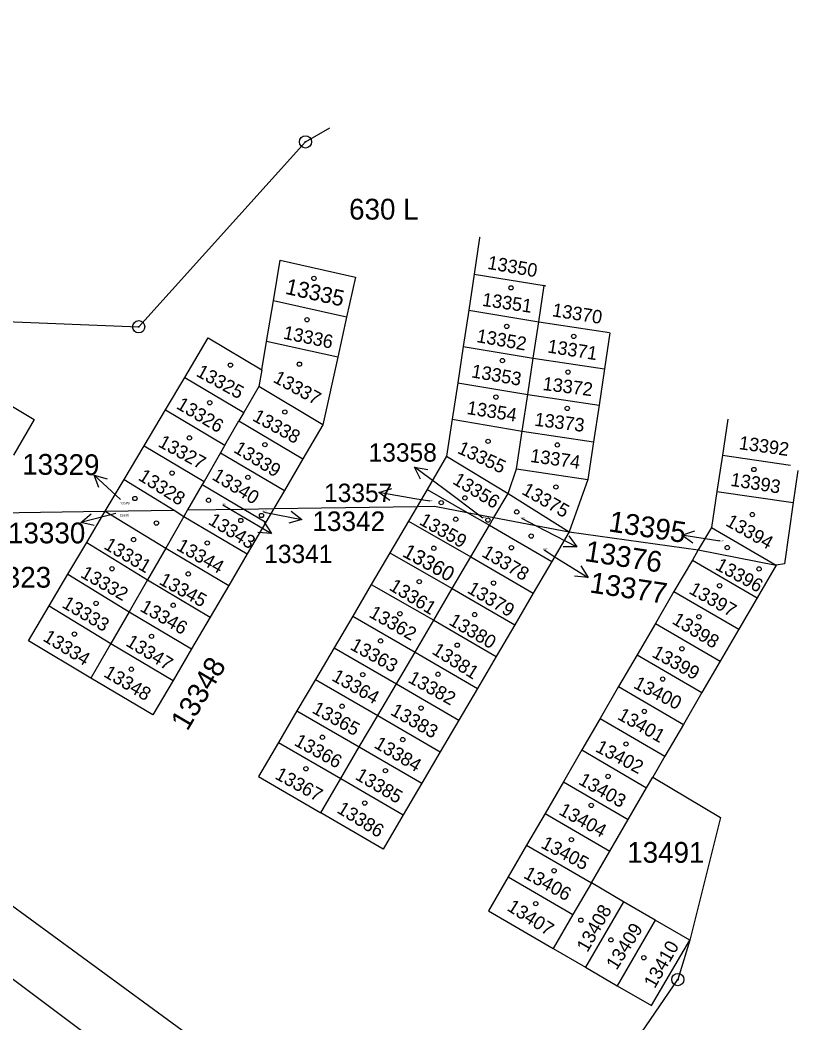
# Model space of a CAD drawing. Extents: x -825057 to -819383, y -1071633 to -1067888.
# Drawn here: x -820277 to -820213.4, y -1071568.9 to -1071486.9 of the extents above; entities that cross this region are included whole.
import ezdxf

# ---------------------------------------------------------------- set-up
doc = ezdxf.new("R2010")
doc.units = 0
for name, color, linetype in [('Vrstva 1', 7, 'Continuous'), ('Vrstva 10', 7, 'Continuous'), ('Vrstva 13', 7, 'Continuous'), ('Vrstva 16', 7, 'Continuous'), ('Vrstva 17', 7, 'Continuous'), ('Vrstva 18', 7, 'Continuous'), ('Vrstva 19', 7, 'Continuous'), ('Vrstva 24', 7, 'Continuous'), ('Vrstva 25', 7, 'Continuous')]:
    doc.layers.add(name, color=color, linetype=linetype)

msp = doc.modelspace()

# ---------------------------------------------------------------- linework, layer by layer
at = {"layer": 'Vrstva 1'}
for p, q in [((-820253.69, -1071496.85), (-820251.69, -1071495.69)), ((-820267.33, -1071511.96), (-820253.69, -1071496.85)), ((-820239.46, -1071504.68), (-820239.91, -1071507.65)), ((-820239.45, -1071504.65), (-820239.46, -1071504.68)), ((-820239.46, -1071504.68), (-820239.4, -1071504.69)), ((-820256.32, -1071509.84), (-820255.75, -1071506.52)), ((-820255.75, -1071506.52), (-820249.6, -1071507.9)), ((-820249.6, -1071507.9), (-820250.33, -1071511.17)), ((-820239.91, -1071507.65), (-820240.35, -1071510.61)), ((-820239.91, -1071507.65), (-820234.17, -1071508.6)), ((-820234.62, -1071511.57), (-820234.17, -1071508.6)), ((-820234.17, -1071508.6), (-820234.16, -1071508.53)), ((-820234.17, -1071508.6), (-820234.04, -1071508.62)), ((-820256.89, -1071513.16), (-820256.32, -1071509.84)), ((-820250.33, -1071511.17), (-820256.32, -1071509.84)), ((-820250.33, -1071511.17), (-820251.05, -1071514.46)), ((-820240.35, -1071510.61), (-820240.8, -1071513.58)), ((-820240.35, -1071510.61), (-820234.62, -1071511.57)), ((-820284.31, -1071511.28), (-820267.33, -1071511.96)), ((-820235.07, -1071514.53), (-820234.62, -1071511.57)), ((-820234.62, -1071511.57), (-820228.83, -1071512.44)), ((-820263.57, -1071516.1), (-820261.65, -1071512.87)), ((-820261.65, -1071512.87), (-820257.25, -1071515.49)), ((-820228.8, -1071512.45), (-820229.24, -1071515.41)), ((-820257.25, -1071515.49), (-820256.89, -1071513.16)), ((-820251.05, -1071514.46), (-820256.89, -1071513.16)), ((-820240.8, -1071513.58), (-820241.25, -1071516.55)), ((-820240.8, -1071513.58), (-820235.07, -1071514.53)), ((-820251.05, -1071514.46), (-820252.28, -1071519.99)), ((-820235.52, -1071517.5), (-820235.07, -1071514.53)), ((-820235.07, -1071514.53), (-820229.24, -1071515.41)), ((-820265.15, -1071518.76), (-820263.57, -1071516.1)), ((-820263.57, -1071516.1), (-820258.73, -1071518.97)), ((-820257.25, -1071515.49), (-820257.52, -1071516.84)), ((-820229.24, -1071515.41), (-820229.69, -1071518.37)), ((-820281.37, -1071516.28), (-820275.87, -1071519.55)), ((-820257.52, -1071516.84), (-820258.73, -1071518.97)), ((-820252.28, -1071519.99), (-820257.52, -1071516.84)), ((-820241.25, -1071516.55), (-820241.7, -1071519.51)), ((-820241.25, -1071516.55), (-820235.52, -1071517.5)), ((-820235.97, -1071520.5), (-820235.52, -1071517.5)), ((-820235.52, -1071517.5), (-820229.69, -1071518.37)), ((-820229.69, -1071518.37), (-820230.14, -1071521.37)), ((-820266.88, -1071521.69), (-820265.15, -1071518.76)), ((-820265.15, -1071518.76), (-820260.28, -1071521.64)), ((-820258.73, -1071518.97), (-820259.14, -1071519.66)), ((-820275.87, -1071519.55), (-820277.57, -1071522.47)), ((-820260.28, -1071521.64), (-820259.14, -1071519.66)), ((-820259.14, -1071519.66), (-820253.9, -1071522.76)), ((-820252.28, -1071519.99), (-820253.9, -1071522.76)), ((-820241.7, -1071519.51), (-820242.16, -1071522.55)), ((-820241.7, -1071519.51), (-820235.97, -1071520.5)), ((-820219.16, -1071519.52), (-820219.61, -1071522.46)), ((-820236.43, -1071523.58), (-820235.97, -1071520.5)), ((-820235.97, -1071520.5), (-820230.14, -1071521.37)), ((-820268.52, -1071524.44), (-820266.88, -1071521.69)), ((-820266.88, -1071521.69), (-820261.98, -1071524.6)), ((-820260.28, -1071521.64), (-820260.64, -1071522.26)), ((-820230.14, -1071521.37), (-820230.6, -1071524.46)), ((-820260.64, -1071522.26), (-820261.98, -1071524.6)), ((-820260.64, -1071522.26), (-820255.42, -1071525.35)), ((-820242.16, -1071522.55), (-820243.75, -1071525.27)), ((-820242.16, -1071522.55), (-820237.13, -1071525.6)), ((-820219.61, -1071522.46), (-820220.07, -1071525.43)), ((-820219.61, -1071522.46), (-820214.04, -1071523.27)), ((-820253.9, -1071522.76), (-820255.42, -1071525.35)), ((-820237.13, -1071525.6), (-820236.43, -1071523.58)), ((-820236.43, -1071523.58), (-820230.6, -1071524.46)), ((-820270.06, -1071527.04), (-820268.52, -1071524.44)), ((-820268.52, -1071524.44), (-820264.44, -1071526.96)), ((-820262.13, -1071524.86), (-820263.33, -1071526.94)), ((-820261.98, -1071524.6), (-820262.13, -1071524.86)), ((-820262.13, -1071524.86), (-820258.74, -1071526.87)), ((-820230.6, -1071524.46), (-820232.13, -1071528.73)), ((-820255.42, -1071525.35), (-820256.28, -1071526.83)), ((-820243.75, -1071525.27), (-820244.57, -1071526.65)), ((-820243.75, -1071525.27), (-820240.47, -1071527.14)), ((-820238.28, -1071527.56), (-820237.13, -1071525.6)), ((-820237.13, -1071525.6), (-820232.13, -1071528.73)), ((-820220.07, -1071525.43), (-820220.51, -1071528.36)), ((-820220.07, -1071525.43), (-820213.81, -1071526.34)), ((-820258.74, -1071526.87), (-820256.28, -1071526.83)), ((-820256.28, -1071526.83), (-820256.94, -1071527.94)), ((-820256.28, -1071526.83), (-820244.57, -1071526.65)), ((-820244.57, -1071526.65), (-820245.27, -1071527.85)), ((-820244.57, -1071526.65), (-820243.15, -1071526.63)), ((-820243.15, -1071526.63), (-820240.47, -1071527.14)), ((-820280.32, -1071527.2), (-820270.06, -1071527.04)), ((-820271.58, -1071529.6), (-820270.06, -1071527.04)), ((-820270.06, -1071527.04), (-820264.44, -1071526.96)), ((-820270.06, -1071527.04), (-820265.12, -1071530.06)), ((-820263.63, -1071527.46), (-820265.12, -1071530.06)), ((-820264.44, -1071526.96), (-820263.63, -1071527.46)), ((-820263.33, -1071526.94), (-820263.63, -1071527.46)), ((-820263.63, -1071527.46), (-820258.45, -1071530.53)), ((-820263.33, -1071526.94), (-820258.74, -1071526.87)), ((-820258.74, -1071526.87), (-820256.94, -1071527.94)), ((-820240.47, -1071527.14), (-820238.65, -1071528.18)), ((-820240.47, -1071527.14), (-820238.28, -1071527.56)), ((-820238.65, -1071528.18), (-820238.28, -1071527.56)), ((-820238.28, -1071527.56), (-820232.13, -1071528.73)), ((-820256.94, -1071527.94), (-820258.45, -1071530.53)), ((-820245.27, -1071527.85), (-820246.79, -1071530.44)), ((-820245.27, -1071527.85), (-820240.17, -1071530.77)), ((-820240.17, -1071530.77), (-820238.65, -1071528.18)), ((-820238.65, -1071528.18), (-820233.55, -1071531.15)), ((-820220.51, -1071528.36), (-820221.58, -1071530.19)), ((-820220.51, -1071528.36), (-820215.21, -1071531.44)), ((-820232.13, -1071528.73), (-820233.55, -1071531.15)), ((-820232.13, -1071528.73), (-820221.58, -1071530.19)), ((-820273.11, -1071532.18), (-820271.58, -1071529.6)), ((-820271.58, -1071529.6), (-820266.62, -1071532.66)), ((-820265.12, -1071530.06), (-820266.62, -1071532.66)), ((-820265.12, -1071530.06), (-820259.97, -1071533.12)), ((-820258.45, -1071530.53), (-820259.97, -1071533.12)), ((-820246.79, -1071530.44), (-820248.31, -1071533.03)), ((-820246.79, -1071530.44), (-820241.69, -1071533.36)), ((-820241.69, -1071533.36), (-820240.17, -1071530.77)), ((-820240.17, -1071530.77), (-820235.07, -1071533.74)), ((-820221.58, -1071530.19), (-820222.06, -1071531.03)), ((-820221.58, -1071530.19), (-820215.21, -1071531.44)), ((-820233.55, -1071531.15), (-820235.07, -1071533.74)), ((-820222.06, -1071531.03), (-820223.57, -1071533.61)), ((-820222.06, -1071531.03), (-820216.77, -1071534.11)), ((-820274.66, -1071534.78), (-820273.11, -1071532.18)), ((-820273.11, -1071532.18), (-820268.12, -1071535.26)), ((-820266.62, -1071532.66), (-820268.12, -1071535.26)), ((-820266.62, -1071532.66), (-820261.48, -1071535.71)), ((-820259.97, -1071533.12), (-820261.48, -1071535.71)), ((-820248.31, -1071533.03), (-820249.83, -1071535.61)), ((-820248.31, -1071533.03), (-820243.2, -1071535.95)), ((-820243.2, -1071535.95), (-820241.69, -1071533.36)), ((-820241.69, -1071533.36), (-820236.59, -1071536.33)), ((-820235.07, -1071533.74), (-820236.59, -1071536.33)), ((-820223.57, -1071533.61), (-820225.08, -1071536.21)), ((-820223.57, -1071533.61), (-820218.27, -1071536.69)), ((-820276.35, -1071537.64), (-820274.66, -1071534.78)), ((-820274.66, -1071534.78), (-820269.61, -1071537.86)), ((-820268.12, -1071535.26), (-820269.61, -1071537.86)), ((-820268.12, -1071535.26), (-820263, -1071538.3)), ((-820261.48, -1071535.71), (-820263, -1071538.3)), ((-820249.83, -1071535.61), (-820251.35, -1071538.2)), ((-820249.83, -1071535.61), (-820244.73, -1071538.55)), ((-820244.73, -1071538.55), (-820243.2, -1071535.95)), ((-820243.2, -1071535.95), (-820238.11, -1071538.92)), ((-820236.59, -1071536.33), (-820238.11, -1071538.92)), ((-820225.08, -1071536.21), (-820226.58, -1071538.79)), ((-820225.08, -1071536.21), (-820219.78, -1071539.29)), ((-820271.23, -1071540.68), (-820276.35, -1071537.64)), ((-820269.61, -1071537.86), (-820271.23, -1071540.68)), ((-820269.61, -1071537.86), (-820264.52, -1071540.89)), ((-820263, -1071538.3), (-820264.52, -1071540.89)), ((-820251.35, -1071538.2), (-820252.87, -1071540.79)), ((-820251.35, -1071538.2), (-820246.25, -1071541.14)), ((-820246.25, -1071541.14), (-820244.73, -1071538.55)), ((-820244.73, -1071538.55), (-820239.64, -1071541.52)), ((-820238.11, -1071538.92), (-820239.64, -1071541.52)), ((-820226.58, -1071538.79), (-820228.09, -1071541.38)), ((-820226.58, -1071538.79), (-820221.28, -1071541.87)), ((-820266.16, -1071543.69), (-820271.23, -1071540.68)), ((-820264.52, -1071540.89), (-820266.16, -1071543.69)), ((-820252.87, -1071540.79), (-820254.39, -1071543.37)), ((-820252.87, -1071540.79), (-820247.77, -1071543.73)), ((-820247.77, -1071543.73), (-820246.25, -1071541.14)), ((-820246.25, -1071541.14), (-820241.15, -1071544.11)), ((-820239.64, -1071541.52), (-820241.15, -1071544.11)), ((-820228.09, -1071541.38), (-820229.59, -1071543.98)), ((-820228.09, -1071541.38), (-820222.79, -1071544.47)), ((-820254.39, -1071543.37), (-820255.91, -1071545.96)), ((-820254.39, -1071543.37), (-820249.29, -1071546.31)), ((-820249.29, -1071546.31), (-820247.77, -1071543.73)), ((-820247.77, -1071543.73), (-820242.67, -1071546.7)), ((-820229.59, -1071543.98), (-820231.1, -1071546.56)), ((-820229.59, -1071543.98), (-820224.3, -1071547.06)), ((-820241.15, -1071544.11), (-820242.67, -1071546.7)), ((-820255.91, -1071545.96), (-820257.54, -1071548.73)), ((-820255.91, -1071545.96), (-820250.81, -1071548.9)), ((-820250.81, -1071548.9), (-820249.29, -1071546.31)), ((-820249.29, -1071546.31), (-820244.19, -1071549.28)), ((-820242.67, -1071546.7), (-820244.19, -1071549.28)), ((-820231.1, -1071546.56), (-820232.61, -1071549.16)), ((-820231.1, -1071546.56), (-820225.8, -1071549.64)), ((-820257.54, -1071548.73), (-820252.45, -1071551.7)), ((-820252.45, -1071551.7), (-820250.81, -1071548.9)), ((-820250.81, -1071548.9), (-820245.71, -1071551.87)), ((-820225.8, -1071549.64), (-820225.3, -1071548.78)), ((-820244.19, -1071549.28), (-820245.71, -1071551.87)), ((-820232.61, -1071549.16), (-820234.11, -1071551.75)), ((-820232.61, -1071549.16), (-820227.31, -1071552.24)), ((-820227.31, -1071552.24), (-820225.8, -1071549.64)), ((-820247.35, -1071554.67), (-820252.45, -1071551.7)), ((-820245.71, -1071551.87), (-820247.35, -1071554.67)), ((-820234.11, -1071551.75), (-820235.62, -1071554.34)), ((-820234.11, -1071551.75), (-820228.81, -1071554.83)), ((-820228.81, -1071554.83), (-820227.31, -1071552.24)), ((-820235.62, -1071554.34), (-820237.13, -1071556.94)), ((-820235.62, -1071554.34), (-820230.32, -1071557.42)), ((-820230.32, -1071557.42), (-820228.81, -1071554.83)), ((-820237.13, -1071556.94), (-820238.74, -1071559.7)), ((-820237.13, -1071556.94), (-820231.83, -1071560.02)), ((-820230.32, -1071557.42), (-820231.83, -1071560.02)), ((-820227.68, -1071558.96), (-820230.32, -1071557.42)), ((-820227.68, -1071558.96), (-820230.79, -1071564.32)), ((-820225.09, -1071560.47), (-820227.68, -1071558.96)), ((-820238.74, -1071559.7), (-820233.44, -1071562.78)), ((-820231.83, -1071560.02), (-820233.44, -1071562.78)), ((-820225.09, -1071560.47), (-820228.21, -1071565.83)), ((-820222.28, -1071562.1), (-820225.09, -1071560.47)), ((-820225.4, -1071567.46), (-820222.28, -1071562.1)), ((-820233.44, -1071562.78), (-820230.79, -1071564.32)), ((-820230.79, -1071564.32), (-820228.21, -1071565.83)), ((-820228.21, -1071565.83), (-820225.4, -1071567.46))]:
    msp.add_line(p, q, dxfattribs=at)
at = {"layer": 'Vrstva 10'}
msp.add_line((-820261.7, -1071577.19), (-820384.69, -1071485.49), dxfattribs=at)
msp.add_spline([(-820648.37, -1071145.75), (-820635.21, -1071175.92), (-820619.77, -1071208), (-820606.88, -1071231.72), (-820592.84, -1071254.92), (-820557.31, -1071306.48), (-820522.72, -1071349.67), (-820487.72, -1071388.36), (-820440.04, -1071434.15), (-820382.01, -1071481.32), (-820258.78, -1071573.12)], degree=3, dxfattribs=at)
at = {"layer": 'Vrstva 13'}
for p, q in [((-820213.43, -1071523.72), (-820213.81, -1071526.34)), ((-820213.81, -1071526.34), (-820214.54, -1071531.35)), ((-820215.21, -1071531.44), (-820216.77, -1071534.11)), ((-820214.54, -1071531.35), (-820215.21, -1071531.44)), ((-820216.77, -1071534.11), (-820218.27, -1071536.69)), ((-820218.27, -1071536.69), (-820219.78, -1071539.29)), ((-820219.78, -1071539.29), (-820221.28, -1071541.87)), ((-820221.28, -1071541.87), (-820222.79, -1071544.47)), ((-820222.79, -1071544.47), (-820224.3, -1071547.06)), ((-820224.3, -1071547.06), (-820225.3, -1071548.78)), ((-820225.3, -1071548.78), (-820219.75, -1071552.07)), ((-820219.75, -1071552.07), (-820222.28, -1071562.1)), ((-820222.28, -1071562.1), (-820223.25, -1071565.33)), ((-820252.56, -1071607.91), (-820223.25, -1071565.33))]:
    msp.add_line(p, q, dxfattribs=at)
at = {"layer": 'Vrstva 16'}
for p, q in [((-820242.38, -1071525.22), (-820244.788, -1071523.431)), ((-820268.81, -1071526.09), (-820270.963, -1071524.088)), ((-820244.74, -1071526.02), (-820247.697, -1071525.516)), ((-820243.53, -1071526.22), (-820244.74, -1071526.02)), ((-820239.19, -1071527.6), (-820242.38, -1071525.22)), ((-820260.44, -1071526.51), (-820259.05, -1071527.34)), ((-820269.2, -1071527.24), (-820272.047, -1071527.972)), ((-820259.05, -1071527.34), (-820256.472, -1071528.875)), ((-820257.13, -1071527.1), (-820256.93, -1071527.14)), ((-820256.93, -1071527.14), (-820253.986, -1071527.716)), ((-820236.02, -1071527.62), (-820234.16, -1071528.58)), ((-820234.16, -1071528.58), (-820231.497, -1071529.961)), ((-820219.97, -1071529.46), (-820222.933, -1071528.992)), ((-820219.78, -1071529.49), (-820219.97, -1071529.46)), ((-820234.18, -1071530.21), (-820233.13, -1071530.87)), ((-820233.13, -1071530.87), (-820230.586, -1071532.46))]:
    msp.add_line(p, q, dxfattribs=at)
for points in [[(-820244.284, -1071524.429), (-820244.788, -1071523.431), (-820243.687, -1071523.626)], [(-820270.579, -1071525.114), (-820270.963, -1071524.088), (-820269.911, -1071524.396)], [(-820246.796, -1071526.177), (-820247.697, -1071525.516), (-820246.628, -1071525.191)], [(-820270.976, -1071528.203), (-820272.047, -1071527.972), (-820271.22, -1071527.253)], [(-820254.871, -1071527.033), (-820253.986, -1071527.716), (-820255.063, -1071528.014)], [(-820257.076, -1071527.934), (-820256.472, -1071528.875), (-820257.587, -1071528.793)], [(-820232.154, -1071529.057), (-820231.497, -1071529.961), (-820232.615, -1071529.944)], [(-820222.024, -1071529.642), (-820222.933, -1071528.992), (-820221.867, -1071528.654)], [(-820231.169, -1071531.506), (-820230.586, -1071532.46), (-820231.699, -1071532.354)]]:
    msp.add_lwpolyline(points, dxfattribs=at)
at = {"layer": 'Vrstva 24'}
for centre, radius in [((-820253.69, -1071496.85), 0.5), ((-820253.69, -1071496.85), 0.0327), ((-820267.33, -1071511.96), 0.5), ((-820267.33, -1071511.96), 0.0327), ((-820223.25, -1071565.33), 0.5), ((-820223.25, -1071565.33), 0.0327)]:
    msp.add_circle(centre, radius, dxfattribs=at)
at = {"layer": 'Vrstva 25'}
for centre in [(-820253, -1071508.01), (-820236.89, -1071508.78), (-820253.57, -1071511.39), (-820237.24, -1071511.93), (-820231.76, -1071512.75), (-820259.83, -1071515.1), (-820254.19, -1071515.02), (-820237.59, -1071514.73), (-820232.23, -1071515.67), (-820238.12, -1071517.71), (-820261.52, -1071518.17), (-820232.29, -1071518.64), (-820255.38, -1071518.93), (-820263.18, -1071521.05), (-820257.01, -1071521.6), (-820238.76, -1071521.33), (-820233.1, -1071521.62), (-820217.03, -1071523.63), (-820264.6, -1071523.92), (-820258.4, -1071524.27), (-820233.22, -1071525.06), (-820267.64, -1071526), (-820261.62, -1071526.14), (-820240.66, -1071525.95), (-820242.59, -1071526.34), (-820258.98, -1071527.8), (-820257.29, -1071527.39), (-820241.41, -1071527.7), (-820238.78, -1071527.77), (-820236.42, -1071527.1), (-820217.16, -1071527.32), (-820265.88, -1071528.01), (-820267.75, -1071529.36), (-820235.24, -1071529.07), (-820261.72, -1071529.64), (-820243.2, -1071530.07), (-820236.86, -1071530.03), (-820219.21, -1071530.01), (-820269.51, -1071531.74), (-820216.61, -1071531.76), (-820263.28, -1071532.17), (-820244.39, -1071532.8), (-820238.32, -1071532.92), (-820219.84, -1071533.13), (-820270.81, -1071534.58), (-820264.51, -1071534.73), (-820245.97, -1071535.42), (-820239.86, -1071535.49), (-820221.53, -1071535.67), (-820272.58, -1071537.08), (-820266.28, -1071537.27), (-820247.55, -1071537.64), (-820241.28, -1071537.99), (-820222.92, -1071538.28), (-820267.93, -1071539.96), (-820249.01, -1071540.4), (-820242.86, -1071540.37), (-820224.49, -1071540.76), (-820250.7, -1071542.98), (-820244.24, -1071543.13), (-820225.99, -1071543.41), (-820252.31, -1071545.52), (-820245.74, -1071545.71), (-820227.49, -1071546.07), (-820253.66, -1071548.09), (-820247.16, -1071548.25), (-820228.95, -1071548.72), (-820248.85, -1071550.9), (-820230.33, -1071551.09), (-820231.95, -1071553.89), (-820233.37, -1071556.43), (-820234.87, -1071559.12), (-820231.18, -1071560.47), (-820228.72, -1071562.08), (-820226.03, -1071563.54)]:
    msp.add_circle(centre, 0.175, dxfattribs=at)

# ---------------------------------------------------------------- texts
at = {"layer": 'Vrstva 16'}
for s, height, p in [('13358', 1.5, (-820248.532, -1071522.99)), ('13357', 1.5, (-820252.175, -1071526.29)), ('13342', 1.6, (-820253.13, -1071528.66)), ('13330', 1.7, (-820278.015, -1071529.67)), ('13341', 1.5, (-820257.066, -1071531.28)), ('13323', 1.7, (-820280.809, -1071533.29))]:
    msp.add_text(s, height=height, dxfattribs=at).set_placement(p)
for s, rotation, p in [('13329', 359.5851, (-820276.864, -1071524.049)), ('13395', 351.2295, (-820228.975, -1071528.679)), ('13376', 351.2547, (-820230.93, -1071531.102)), ('13377', 351.3744, (-820230.525, -1071533.673)), ('13348', 59.4, (-820263.347, -1071545.074))]:
    msp.add_text(s, height=1.7, rotation=rotation, dxfattribs=at).set_placement(p)
at = {"layer": 'Vrstva 17'}
msp.add_text('630 L', height=1.7, dxfattribs=at).set_placement((-820250.129, -1071503.2))
at = {"layer": 'Vrstva 18'}
msp.add_text('13491', height=1.7, dxfattribs=at).set_placement((-820227.393, -1071555.78))
at = {"layer": 'Vrstva 19'}
for s, height, rotation, p in [('13350', 1.1, 350.1, (-820238.87, -1071507.22)), ('13335', 1.3, 347.4, (-820255.41, -1071509.26)), ('13351', 1.1, 351.9, (-820239.3, -1071510.25)), ('13370', 1.1, 351, (-820233.57, -1071511.1)), ('13336', 1.1, 348.3, (-820255.57, -1071512.93)), ('13352', 1.1, 350.1, (-820239.76, -1071513.21)), ('13371', 1.1, 351, (-820233.96, -1071514.06)), ('13325', 1.1, 331.2, (-820262.71, -1071515.94)), ('13353', 1.1, 350.1, (-820240.18, -1071516.09)), ('13337', 1.1, 331.2, (-820256.41, -1071516.44)), ('13372', 1.1, 352.8, (-820234.34, -1071517.13)), ('13326', 1.1, 329.4, (-820264.33, -1071518.59)), ('13354', 1.1, 351, (-820240.55, -1071519.09)), ('13338', 1.1, 331.2, (-820258.1, -1071519.59)), ('13373', 1.1, 352.8, (-820235.01, -1071520.05)), ('13327', 1.1, 331.2, (-820265.82, -1071521.7)), ('13392', 1.1, 351.9, (-820218.3, -1071521.96)), ('13339', 1.1, 328.5, (-820259.64, -1071522.17)), ('13355', 1.1, 334.8, (-820241.35, -1071522.25)), ('13374', 1.1, 351.9, (-820235.36, -1071523.01)), ('13328', 1.1, 327.6, (-820267.44, -1071524.43)), ('13340', 1.1, 328.5, (-820261.41, -1071524.39)), ('13356', 1.1, 328.5, (-820241.74, -1071524.74)), ('13393', 1.1, 351, (-820218.99, -1071524.96)), ('13375', 1.1, 330.3, (-820236.09, -1071525.59)), ('13343', 1.1, 328.5, (-820261.72, -1071528.04)), ('13359', 1.1, 330.3, (-820244.47, -1071528.07)), ('13394', 1.1, 330.3, (-820219.42, -1071528.17)), ('13331', 1.1, 329.4, (-820270.25, -1071530.06)), ('13344', 1.1, 330.3, (-820264.32, -1071530.16)), ('13360', 1.2, 331.2, (-820245.85, -1071530.69)), ('13378', 1.1, 329.4, (-820239.36, -1071530.69)), ('13332', 1.1, 330.3, (-820272.16, -1071532.39)), ('13396', 1.1, 331.2, (-820220.27, -1071531.75)), ('13345', 1.1, 331.2, (-820265.74, -1071532.96)), ('13361', 1.1, 328.5, (-820246.93, -1071533.42)), ('13379', 1.1, 329.4, (-820240.55, -1071533.65)), ('13397', 1.1, 330.3, (-820222.42, -1071533.71)), ('13333', 1.1, 329.4, (-820273.68, -1071534.85)), ('13346', 1.1, 330.3, (-820267.3, -1071535.15)), ('13362', 1.1, 330.3, (-820248.58, -1071535.64)), ('13380', 1.1, 329.4, (-820242.05, -1071536.26)), ('13398', 1.1, 328.5, (-820223.8, -1071536.17)), ('13334', 1.1, 328.5, (-820275.23, -1071537.58)), ('13347', 1.1, 328.5, (-820268.46, -1071537.98)), ('13363', 1.1, 331.2, (-820250.12, -1071538.29)), ('13381', 1.1, 327.6, (-820243.43, -1071538.64)), ('13399', 1.1, 331.2, (-820225.45, -1071538.9)), ('13348', 1.1, 329.4, (-820270.27, -1071540.51)), ('13364', 1.1, 330.3, (-820251.62, -1071540.83)), ('13382', 1.1, 331.2, (-820245.39, -1071540.98)), ('13400', 1.1, 333, (-820226.95, -1071541.45)), ('13365', 1.1, 331.2, (-820253.23, -1071543.48)), ('13383', 1.1, 330.3, (-820246.82, -1071543.63)), ('13401', 1.1, 330.3, (-820228.26, -1071543.99)), ('13366', 1.1, 331.2, (-820254.69, -1071546.13)), ('13384', 1.1, 329.4, (-820248.16, -1071546.32)), ('13402', 1.1, 332.1, (-820230.06, -1071546.64)), ('13367', 1.1, 331.2, (-820256.27, -1071548.86)), ('13385', 1.1, 329.4, (-820249.7, -1071548.9)), ('13403', 1.1, 330.3, (-820231.45, -1071549.3)), ('13386', 1.1, 328.5, (-820251.2, -1071551.63)), ('13404', 1.1, 331.2, (-820233.06, -1071551.78)), ('13405', 1.1, 332.1, (-820234.52, -1071554.51)), ('13406', 1.1, 331.2, (-820235.94, -1071556.97)), ('13407', 1.1, 327.6, (-820237.29, -1071559.62)), ('13408', 1.1, 60.3, (-820230.64, -1071563.16)), ('13409', 1.1, 57.6, (-820228.26, -1071564.62)), ('13410', 1.1, 60.3, (-820225.14, -1071566.12))]:
    msp.add_text(s, height=height, rotation=rotation, dxfattribs=at).set_placement(p)
for s, height, p in [('13329', 0.2, (-820268.85, -1071526.49)), ('13341', 0.1, (-820260.556, -1071526.51)), ('13357', 0.1, (-820243.66, -1071526.22)), ('13330', 0.2, (-820268.89, -1071527.46)), ('13342', 0.1, (-820257.263, -1071527.1)), ('13358', 0.1, (-820239.323, -1071527.6)), ('13376', 0.1, (-820236.148, -1071527.62)), ('13377', 0.1, (-820234.306, -1071530.21)), ('13395', 0.1, (-820219.912, -1071529.49))]:
    msp.add_text(s, height=height, dxfattribs=at).set_placement(p)

doc.saveas('drawing.dxf')
